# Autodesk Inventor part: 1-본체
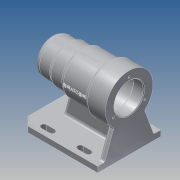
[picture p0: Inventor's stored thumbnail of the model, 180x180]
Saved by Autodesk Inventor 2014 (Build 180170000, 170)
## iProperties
Created: 2017-09
Part Number: 1-본체
Material: 알루미늄 6061
Document SubType Name: Modeling
Designer: kb542-15
Density: 2.71 g/cm^3
Appearance: 알루미늄 - 평지
Mass: 696.875 g
Surface Area: 709.243 cm^2
Volume: 257.15 cm^3
Author: kb542-15
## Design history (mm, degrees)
sketch "스케치1"
  geometry: L1 (-56, 0)-(56, 0); L2 (-56, 0)-(-56, 25); L3 (-56, 25)-(-31, 25); L4 (-31, 25)-(-31, 27); L5 (-31, 27)-(-11, 27); L6 (-11, 27)-(-11, 30); L7 (-11, 30)-(28, 30); L8 (28, 30)-(28, 34); L9 (28, 34)-(56, 34); L10 (56, 34)-(56, 21); L11 (56, 21)-(41, 21); L12 (41, 21)-(41, 24); L13 (41, 24)-(-13, 24); L14 (-13, 24)-(-13, 21); L15 (-13, 21)-(-25, 21); L16 (-25, 21)-(-25, 17.5); L17 (-25, 17.5)-(-43, 17.5); L18 (-43, 17.5)-(-43, 16); L19 (-43, 16)-(-47, 16); L20 (-47, 16)-(-47, 10.5); L21 (-47, 10.5)-(-50, 10.5); L22 (-50, 10.5)-(-50, 0); 2 further points
  constraints: 44 end point, 13 parallel, 7 perpendicular, 1 coincident, 1 collinear, 1 horizontal, 1 midpoint, 1 point on line, 1 vertical alignment
  dimensions: "d0" = 112 distance of L1.start L1.end; "d1" = 25 distance of L2.end L3.end; "d2" = 45 distance from line of L2 L6.end; "d3" = 84 distance from line of L8.end L2; "d4" = 21 diameter of L21 L1; "d5" = 32 diameter of L19 L1; "d6" = 35 diameter of L17 L1; "d7" = 42 diameter of L15 L1; "d8" = 48 diameter of L13 L1; "d9" = 42 diameter of L11 L1; "d10" = 50 diameter of L3 L1; "d11" = 54 diameter of L5 L1; "d12" = 60 diameter of L7 L1; "d13" = 68 diameter of L9 L1; "d14" = 15 distance of L10.end L11.end; "d15" = 54 distance of L12.end L13.end; "d16" = 12 distance of L14.end L15.end; "d17" = 18 distance of L16.end L17.end; "d18" = 4 distance of L18.end L19.end; "d19" = 3 distance of L20.end L21.end
revolve "회전1" sketch "스케치1" stored, may be unused: angle "d20" = 90 deg
node "작업 평면1"
sketch "스케치2"
  geometry: L1 (-56, -45)-(56, -45); L2 (56, -45)-(56, 45); L3 (56, 45)-(-56, 45); L4 (-56, 45)-(-56, -45); L5 (-56, -45)-(56, 45); L6 (56, -45)-(-56, 45); 1 further point
  constraints: 12 end point, 2 midpoint, 2 parallel, 1 horizontal, 1 perpendicular
  dimensions: "d22" = 112 distance of L2.end L3.end; "d23" = 90 distance of L1.end L2.end
extrude "돌출1" join sketch "스케치2" distance "d24" = 8; taper "d25" = 0 deg
sketch "스케치3"
  geometry: L1 (70, -45)-(70, 45) reference; L2 (70, 45)-(62, 45) reference; L3 (62, -45)-(62, 45) reference; L4 (70, -45)-(62, -45) reference; L5 (62, -35)-(26.008, -21.9); L6 (62, 35)-(26.008, 21.9); A1 r 34 centre (0, 0) between (26.008, -21.9) and (26.008, 21.9) reference
  constraints: 4 end point, 2 point on circle, 2 point on line
  dimensions: "d26" = 110 deg angle of L3 L5; "d27" = 110 deg angle of L3 L6; "d28" = 10 distance from line of L5.start L4; "d29" = 10 distance of L2.end L6.start
extrude "돌출2" join sketch "스케치3" distance "d30" = 8; taper "d31" = 0 deg
sketch "스케치4"
  geometry: L1 (56, 25)-(56, -25) reference; L2 (56, -25)-(31, -25) reference; L3 (31, -25)-(31, -27) reference; L4 (31, -27)-(11, -27) reference; L5 (11, -27)-(11, -30) reference; L6 (11, -30)-(-28, -30) reference; L7 (-28, -30)-(-28, -34) reference; L8 (-28, -34)-(-48, -34) reference; L9 (-48, -34)-(-48, -62) reference; L10 (-48, -62)-(56, -62) reference; L11 (56, -62)-(56, -70) reference; L12 (56, -70)-(-56, -70) reference; L13 (-56, -70)-(-56, -21) reference; L14 (-56, -21)-(-41, -21) reference; L15 (-41, -21)-(-41, -24) reference; L16 (-41, -24)-(13, -24) reference; L17 (13, -24)-(13, -21) reference; L18 (13, -21)-(25, -21) reference; L19 (25, -21)-(25, -17.5) reference; L20 (25, -17.5)-(43, -17.5) reference; L21 (43, -17.5)-(43, -16) reference; L22 (43, -16)-(47, -16) reference; L23 (47, -16)-(47, -10.5) reference; L24 (47, -10.5)-(50, -10.5) reference; L25 (50, -10.5)-(50, 10.5) reference; L26 (50, 10.5)-(47, 10.5) reference; L27 (47, 10.5)-(47, 16) reference; L28 (47, 16)-(43, 16) reference; L29 (43, 16)-(43, 17.5) reference; L30 (43, 17.5)-(25, 17.5) reference; L31 (25, 17.5)-(25, 21) reference; L32 (25, 21)-(13, 21) reference; L33 (13, 21)-(13, 24) reference; L34 (13, 24)-(-41, 24) reference; L35 (-41, 24)-(-41, 21) reference; L36 (-41, 21)-(-56, 21) reference; L37 (-56, 21)-(-56, 34) reference; L38 (-56, 34)-(-28, 34) reference; L39 (-28, 34)-(-28, 30) reference; L40 (-28, 30)-(11, 30) reference; L41 (11, 30)-(11, 27) reference; L42 (11, 27)-(31, 27) reference; L43 (31, 27)-(31, 25) reference; L44 (31, 25)-(56, 25) reference; L45 (34, -62)-(24.622, -27); 1 further point
  constraints: 2 end point, 2 point on line
  dimensions: "d32" = 22 distance from line of L45.start L11; "d33" = 105 deg angle of L45 L10
feature "리브1" sketch "스케치4" dims "d34" = 1, "d35" = 8, "d36" = 0, "d37" = 0, "d38" = 1, "d39" = 1
sketch "스케치5"
  geometry: L1 (48, -4)-(-34, -4) reference; L2 (56, -45)-(56, -35) reference; L3 (32, -34)-(20, -34); L4 (32, -30)-(20, -30); L5 (20, -38)-(32, -38); L6 (-20, -34)-(-32, -34); L7 (-20, -30)-(-32, -30); L8 (-32, -38)-(-20, -38); A1 r 4 centre (32, -34) between (32, -38) and (32, -30); A2 r 4 centre (20, -34) between (20, -30) and (20, -38); A3 r 4 centre (-20, -34) between (-20, -38) and (-20, -30); A4 r 4 centre (-32, -34) between (-32, -30) and (-32, -38); 3 further points
  constraints: 16 end point, 8 point on circle, 8 tangent, 4 centre point, 4 parallel, 2 midpoint, 1 horizontal alignment
  dimensions: "d40" = 24 distance from line of L2 L3.start; "d41" = 12 distance of L3.start L3.end; "d42" = 4 radius of A1; "d43" = 34 vertical distance of point (0, 0) L3.start; "d44" = 4 radius of A4; "d45" = 12 distance of L6.start L6.end; "d46" = 40 distance of L3.end L6.start
extrude "돌출3" cut sketch "스케치5" stored distance "d47" = 8; taper "d48" = 0 deg
chamfer "모따기1" distance "d49" = 12; stored, may be unused: second distance "d50" = 2, angle "d51" = 45 deg
sketch "스케치6"
  geometry: C1 r 21 at (-70, 45) reference; 1 further point
  constraints: 1 horizontal alignment
  dimensions: "d52" = 26 distance of point (-96, 45) C1.centre
hole "구멍1" sketch "스케치6" at (-96, 45) diameter "d53" = 3.242; stored, may be unused: countersink angle "d57" = 90 deg, drill point angle "d59" = 118 deg; dims "d54" = 8, "d55" = 4, "d56" = 2, "d58" = 11
fillet "모깎기1" dims "d63" = 3
fillet "모깎기2" dims "d64" = 3
fillet "모깎기3" dims "d65" = 3
fillet "모깎기4" dims "d66" = 3
fillet "모깎기5" dims "d67" = 9
chamfer "모따기2" distance "d68" = 1; stored, may be unused: second distance "d69" = 2, angle "d70" = 45 deg
node "작업 평면2"
sketch "스케치7"
  geometry: L1 (47.5, -24.711)-(47.5, 34) reference; 2 further points
  constraints: 1 horizontal alignment, 1 other
  dimensions: "d71" = 48 distance from line of L1 point (-0.5, 0)
feature "엠보싱1" sketch "스케치7" dims "d0" = 112, "d1" = 25, "d2" = 45, "d3" = 84, "d4" = 21, "d5" = 32, "d6" = 35, "d7" = 42, "d8" = 48, "d9" = 42, "d10" = 50, "d11" = 54, "d12" = 60, "d13" = 68, "d14" = 15, "d15" = 54, "d16" = 12, "d17" = 18, "d18" = 4, "d19" = 3, "d72" = 0.5, "d73" = 0
fillet "모깎기6" dims "d74" = 0.3
node "솔리드1"
mirror "대칭1"
pattern_circular "원형 패턴1" dims angle "d61" = 360 deg
node "투영된 루프1"
node "절단 모서리 투영1"
